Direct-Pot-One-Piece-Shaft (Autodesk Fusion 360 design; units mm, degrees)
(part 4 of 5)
work_plane "WorkPlane18" AlongDistance 3.9 ExtraOffset 0
sketch "Follower horizontal bore 45 degree roof" plane through (3.9, 0, 0) normal (1, 0, 0) x axis (0, 0, -1)
  line L1 (-14.9345, -32.0655) -> (-14.9345, -37.9345)
  line L2 (-17.869, -35) -> (-14.9345, -32.0655)
  line L3 (-14.9345, -37.9345) -> (-17.869, -35)
extrude "Extrude18" cut sketch "Follower horizontal bore 45 degree roof" along normal blind 16.2
work_plane "WorkPlane19" AlongDistance 3.9 ExtraOffset 0
sketch "Follower horizontal bore 45 degree roof (1)" plane through (3.9, 0, 0) normal (1, 0, 0) x axis (0, 0, -1)
  line L1 (-13.2021, 1.2021) -> (-13.2021, -1.2021)
  line L2 (-14.4042, 0) -> (-13.2021, 1.2021)
  line L3 (-13.2021, -1.2021) -> (-14.4042, 0)
extrude "Extrude19" cut sketch "Follower horizontal bore 45 degree roof (1)" along normal blind 16.2
work_plane "WorkPlane8" AlongDistance 49.65 ExtraOffset 0
sketch "Continuous support beneath lower output prong" plane through (49.65, 0, 0) normal (1, 0, 0) x axis (0, 0, -1)
  line L1 (-57, 2) -> (-57, -2)
  line L2 (-61, 2) -> (-57, 2)
  line L3 (-61, -2) -> (-61, 2)
  line L4 (-57, -2) -> (-61, -2)
extrude "Extrude8" add sketch "Continuous support beneath lower output prong" along normal blind 9
work_plane "WorkPlane11" AlongDistance 9 ExtraOffset 0
sketch "Upright grip head pocket roof" plane through (9, 0, 0) normal (1, 0, 0) x axis (0, 0, -1)
  line L1 (-182.192, -2.192) -> (-182.192, 2.192)
  line L2 (-184.3841, 0) -> (-182.192, -2.192)
  line L3 (-182.192, 2.192) -> (-184.3841, 0)
extrude "Extrude10" cut sketch "Upright grip head pocket roof" along normal blind 16
work_plane "WorkPlane12" AlongDistance 9 ExtraOffset 0
sketch "Upright grip head pocket roof (1)" plane through (9, 0, 0) normal (1, 0, 0) x axis (0, 0, -1)
  line L1 (-192.192, -2.192) -> (-192.192, 2.192)
  line L2 (-194.3841, 0) -> (-192.192, -2.192)
  line L3 (-192.192, 2.192) -> (-194.3841, 0)
extrude "Extrude11" cut sketch "Upright grip head pocket roof (1)" along normal blind 16
work_plane "WorkPlane19" AlongDistance -5 ExtraOffset 0
sketch "Direct cap-head rotor clamp seat" plane through (-5, 0, 0) normal (1, 0, 0) x axis (0, 0, -1)
  line L1 (-60, 22.5) -> (-60, 22)
  line L2 (-70, 22.5) -> (-60, 22.5)
  line L3 (-70, 22) -> (-70, 22.5)
  line L4 (-60, 22) -> (-70, 22)
extrude "Extrude19" add sketch "Direct cap-head rotor clamp seat" along normal blind 10
work_plane "WorkPlane20" AlongDistance 21.9 ExtraOffset 0
sketch "Restore rotor screw through raised seat" plane through (0, 21.9, 0) normal (0, 1, 0) x axis (1, 0, 0)
  circle C1 centre (0, -65) radius 1.7
extrude "Extrude20" cut sketch "Restore rotor screw through raised seat" along normal blind 0.7
work_plane "WorkPlane1" AlongDistance -39.35 ExtraOffset 0
sketch "Main shaft cap M3x8 cap head" plane through (-39.35, 0, 0) normal (1, 0, 0) x axis (0, 0, -1)
  circle C1 centre (-65, 0) radius 1.5
extrude "Extrude1" new body sketch "Main shaft cap M3x8 cap head" along normal blind 8 bodies "HARDWARE Main shaft cap M3x8 cap head"
work_plane "WorkPlane2" AlongDistance -42.35 ExtraOffset 0
sketch "Button head" plane through (-42.35, 0, 0) normal (1, 0, 0) x axis (0, 0, -1)
  circle C1 centre (-65, 0) radius 2.75
extrude "Extrude2" add sketch "Button head" along normal blind 3
work_plane "WorkPlane1" AlongDistance 2 ExtraOffset 0
sketch "Cam M3x10 cap head -45" plane through (2, 0, 0) normal (1, 0, 0) x axis (0, 0, -1)
  circle C1 centre (-39.5442, 25.4558) radius 1.5
extrude "Extrude1" new body sketch "Cam M3x10 cap head -45" along normal blind 10 bodies "HARDWARE Cam M3x10 cap head -45"
work_plane "WorkPlane2" AlongDistance 12 ExtraOffset 0
sketch "Button head" plane through (12, 0, 0) normal (1, 0, 0) x axis (0, 0, -1)
  circle C1 centre (-39.5442, 25.4558) radius 2.75
extrude "Extrude2" add sketch "Button head" along normal blind 3
work_plane "WorkPlane1" AlongDistance 2 ExtraOffset 0
sketch "Cam M3x10 cap head 0" plane through (2, 0, 0) normal (1, 0, 0) x axis (0, 0, -1)
  circle C1 centre (-29, 0) radius 1.5
extrude "Extrude1" new body sketch "Cam M3x10 cap head 0" along normal blind 10 bodies "HARDWARE Cam M3x10 cap head 0"
work_plane "WorkPlane2" AlongDistance 12 ExtraOffset 0
sketch "Button head" plane through (12, 0, 0) normal (1, 0, 0) x axis (0, 0, -1)
  circle C1 centre (-29, 0) radius 2.75
extrude "Extrude2" add sketch "Button head" along normal blind 3
work_plane "WorkPlane1" AlongDistance 2 ExtraOffset 0
sketch "Cam M3x10 cap head 45" plane through (2, 0, 0) normal (1, 0, 0) x axis (0, 0, -1)
  circle C1 centre (-39.5442, -25.4558) radius 1.5
extrude "Extrude1" new body sketch "Cam M3x10 cap head 45" along normal blind 10 bodies "HARDWARE Cam M3x10 cap head 45"
work_plane "WorkPlane2" AlongDistance 12 ExtraOffset 0
sketch "Button head" plane through (12, 0, 0) normal (1, 0, 0) x axis (0, 0, -1)
  circle C1 centre (-39.5442, -25.4558) radius 2.75
extrude "Extrude2" add sketch "Button head" along normal blind 3
work_plane "WorkPlane1" AlongDistance 0 ExtraOffset 0
sketch "Roller axle M3x20 cap head" plane through (0, 0, 0) normal (1, 0, 0) x axis (0, 0, -1)
  circle C1 centre (-12, 0) radius 1.5
extrude "Extrude1" new body sketch "Roller axle M3x20 cap head" along normal blind 20 bodies "HARDWARE Roller axle M3x20 cap head"
work_plane "WorkPlane2" AlongDistance 20 ExtraOffset 0
sketch "Button head" plane through (20, 0, 0) normal (1, 0, 0) x axis (0, 0, -1)
  circle C1 centre (-12, 0) radius 2.75
extrude "Extrude2" add sketch "Button head" along normal blind 3
work_plane "WorkPlane1" AlongDistance -36 ExtraOffset 0
sketch "Crossblock M3x20 cap head (-62, -1)" plane through (-36, 0, 0) normal (1, 0, 0) x axis (0, 0, -1)
  circle C1 centre (-53.5, -62) radius 1.5
extrude "Extrude1" new body sketch "Crossblock M3x20 cap head (-62, -1)" along normal blind 20 bodies "HARDWARE Crossblock M3x20 cap head (-62, -1)"
work_plane "WorkPlane2" AlongDistance -39 ExtraOffset 0
sketch "Button head" plane through (-39, 0, 0) normal (1, 0, 0) x axis (0, 0, -1)
  circle C1 centre (-53.5, -62) radius 2.75
extrude "Extrude2" add sketch "Button head" along normal blind 3
work_plane "WorkPlane1" AlongDistance 16 ExtraOffset 0
sketch "Crossblock M3x20 cap head (-62, 1)" plane through (16, 0, 0) normal (1, 0, 0) x axis (0, 0, -1)
  circle C1 centre (-53.5, -62) radius 1.5
extrude "Extrude1" new body sketch "Crossblock M3x20 cap head (-62, 1)" along normal blind 20 bodies "HARDWARE Crossblock M3x20 cap head (-62, 1)"
work_plane "WorkPlane2" AlongDistance 36 ExtraOffset 0
sketch "Button head" plane through (36, 0, 0) normal (1, 0, 0) x axis (0, 0, -1)
  circle C1 centre (-53.5, -62) radius 2.75
extrude "Extrude2" add sketch "Button head" along normal blind 3
work_plane "WorkPlane1" AlongDistance -36 ExtraOffset 0
sketch "Crossblock M3x20 cap head (-70, -1)" plane through (-36, 0, 0) normal (1, 0, 0) x axis (0, 0, -1)
  circle C1 centre (-53.5, -70) radius 1.5
extrude "Extrude1" new body sketch "Crossblock M3x20 cap head (-70, -1)" along normal blind 20 bodies "HARDWARE Crossblock M3x20 cap head (-70, -1)"
work_plane "WorkPlane2" AlongDistance -39 ExtraOffset 0
sketch "Button head" plane through (-39, 0, 0) normal (1, 0, 0) x axis (0, 0, -1)
  circle C1 centre (-53.5, -70) radius 2.75
extrude "Extrude2" add sketch "Button head" along normal blind 3
work_plane "WorkPlane1" AlongDistance 16 ExtraOffset 0
sketch "Crossblock M3x20 cap head (-70, 1)" plane through (16, 0, 0) normal (1, 0, 0) x axis (0, 0, -1)
  circle C1 centre (-53.5, -70) radius 1.5
extrude "Extrude1" new body sketch "Crossblock M3x20 cap head (-70, 1)" along normal blind 20 bodies "HARDWARE Crossblock M3x20 cap head (-70, 1)"
work_plane "WorkPlane2" AlongDistance 36 ExtraOffset 0
sketch "Button head" plane through (36, 0, 0) normal (1, 0, 0) x axis (0, 0, -1)
  circle C1 centre (-53.5, -70) radius 2.75
extrude "Extrude2" add sketch "Button head" along normal blind 3
work_plane "WorkPlane1" AlongDistance 6.5 ExtraOffset 0
sketch "Rotor clamp M3x16 cap head" plane through (0, 6.5, 0) normal (0, 1, 0) x axis (1, 0, 0)
  circle C1 centre (0, -65) radius 1.5
extrude "Extrude1" new body sketch "Rotor clamp M3x16 cap head" along normal blind 16 bodies "HARDWARE Rotor clamp M3x16 cap head"
work_plane "WorkPlane2" AlongDistance 22.5 ExtraOffset 0
sketch "Button head" plane through (0, 22.5, 0) normal (0, 1, 0) x axis (1, 0, 0)
  circle C1 centre (0, -65) radius 2.75
extrude "Extrude2" add sketch "Button head" along normal blind 3
work_plane "WorkPlane20" AlongDistance 3.9 ExtraOffset 0
sketch "Restore axle bore after adding print feet" plane through (3.9, 0, 0) normal (1, 0, 0) x axis (0, 0, -1)
  circle C1 centre (-12, 0) radius 1.7
extrude "Extrude20" cut sketch "Restore axle bore after adding print feet" along normal blind 16.2
work_plane "WorkPlane21" AlongDistance 3.9 ExtraOffset 0
sketch "Restore nut installation recess after print foot" plane through (3.9, 0, 0) normal (1, 0, 0) x axis (0, 0, -1)
  line L1 (-14.9, 1.6743) -> (-12, 3.3486)
  line L2 (-14.9, -1.6743) -> (-14.9, 1.6743)
  line L3 (-12, -3.3486) -> (-14.9, -1.6743)
  line L4 (-9.1, -1.6743) -> (-12, -3.3486)
  line L5 (-9.1, 1.6743) -> (-9.1, -1.6743)
  line L6 (-12, 3.3486) -> (-9.1, 1.6743)
extrude "Extrude21" cut sketch "Restore nut installation recess after print foot" along normal blind 1.6
work_plane "WorkPlane3" AlongDistance 8 ExtraOffset 0
sketch "Retain one mm preload travel before head meets collar" plane through (8, 0, 0) normal (1, 0, 0) x axis (0, 0, -1)
  line L1 (-56, -51) -> (-56, -59)
  line L2 (-57.1, -51) -> (-56, -51)
  line L3 (-57.1, -59) -> (-57.1, -51)
  line L4 (-56, -59) -> (-57.1, -59)
extrude "Extrude3" cut sketch "Retain one mm preload travel before head meets collar" along normal blind 8
work_plane "WorkPlane63" AlongDistance 20.8 ExtraOffset 0
sketch "Clear stocked carriage screw tip beyond insert" plane through (0, 20.8, 0) normal (0, 1, 0) x axis (1, 0, 0)
  circle C1 centre (60.15, -65) radius 1.7
extrude "Extrude63" cut sketch "Clear stocked carriage screw tip beyond insert" along normal blind 0.6
work_plane "WorkPlane64" AlongDistance -21.4 ExtraOffset 0
sketch "Clear stocked carriage screw tip beyond insert (1)" plane through (0, -21.4, 0) normal (0, 1, 0) x axis (1, 0, 0)
  circle C1 centre (60.15, -65) radius 1.7
extrude "Extrude64" cut sketch "Clear stocked carriage screw tip beyond insert (1)" along normal blind 0.6
work_plane "WorkPlane22" AlongDistance -2.5 ExtraOffset 0
sketch "Support-free lower ramp under left inner-race pad" plane through (0, -2.5, 0) normal (0, 1, 0) x axis (1, 0, 0)
  line L1 (8.1, -9.5) -> (7, -9.5)
  line L2 (8.1, -10.7) -> (8.1, -9.5)
  line L3 (7, -9.6) -> (8.1, -10.7)
  line L4 (7, -9.5) -> (7, -9.6)
extrude "Extrude22" cut sketch "Support-free lower ramp under left inner-race pad" along normal blind 5
work_plane "WorkPlane23" AlongDistance -2.5 ExtraOffset 0
sketch "Support-free lower ramp under right inner-race pad" plane through (0, -2.5, 0) normal (0, 1, 0) x axis (1, 0, 0)
  line L1 (17, -9.5) -> (15.9, -9.5)
  line L2 (17, -9.6) -> (17, -9.5)
  line L3 (15.9, -10.7) -> (17, -9.6)
  line L4 (15.9, -9.5) -> (15.9, -10.7)
extrude "Extrude23" cut sketch "Support-free lower ramp under right inner-race pad" along normal blind 5
ground "Pin94"
ground "Pin95"
ground "Pin96"
ground "Pin97"
ground "Pin98"
ground "Pin99"
ground "Pin100"
ground "Pin101"
ground "Pin102"
ground "Pin103"
ground "Pin104"
ground "Pin105"
ground "Pin106"
ground "Pin107"
ground "Pin108"
ground "Pin109"
ground "Pin110"
ground "Pin111"
ground "Pin112"
ground "Pin113"
ground "Pin114"
ground "Pin115"
ground "Pin116"
ground "Pin120"
ground "Pin121"
ground "Pin122"
ground "Pin123"
ground "Unpin124"
ground "Unpin125"
ground "Unpin126"
ground "Unpin127"
ground "Unpin128"
ground "Unpin129"
ground "Unpin130"
ground "Unpin131"
ground "Unpin132"
ground "Unpin133"
ground "Unpin134"
ground "Unpin135"
ground "Unpin136"
ground "Unpin137"
ground "Unpin138"
ground "Unpin139"
ground "Unpin140"
ground "Unpin141"
ground "Unpin142"
ground "Unpin143"
ground "Unpin144"
ground "Unpin145"
ground "Unpin146"
ground "Unpin147"
ground "Unpin148"
ground "Unpin149"
ground "Unpin150"
ground "Unpin151"
ground "Unpin152"
ground "Unpin153"
ground "Unpin154"
ground "Unpin155"
ground "Unpin156"
ground "Unpin160"
ground "Unpin161"
ground "Unpin162"
ground "Unpin163"
split "Split1" bodies "P04 Right bush upper half"
work_plane "WorkPlane68" AlongDistance -36.1 ExtraOffset 0
sketch "Remove former rail tab before recess" plane through (-36.1, 0, 0) normal (1, 0, 0) x axis (0, 0, -1)
  line L1 (-54.9, -74.5) -> (-54.9, -96)
  line L2 (-64.2, -74.5) -> (-54.9, -74.5)
  line L3 (-64.2, -96) -> (-64.2, -74.5)
  line L4 (-54.9, -96) -> (-64.2, -96)
extrude "Extrude68" cut sketch "Remove former rail tab before recess" along normal blind 12.2
work_plane "WorkPlane69" AlongDistance -36 ExtraOffset 0
sketch "Continuous recessed hanging tower" plane through (-36, 0, 0) normal (1, 0, 0) x axis (0, 0, -1)
  line L1 (-55, -63) -> (-55, -74.5)
  line L2 (-99, -63) -> (-55, -63)
  line L3 (-99, -74.5) -> (-99, -63)
  line L4 (-55, -74.5) -> (-99, -74.5)
extrude "Extrude69" add sketch "Continuous recessed hanging tower" along normal blind 12
work_plane "WorkPlane70" AlongDistance -36 ExtraOffset 0
sketch "Top rail seat unchanged after 35 mm drop" plane through (-36, 0, 0) normal (1, 0, 0) x axis (0, 0, -1)
  line L1 (-90, -63) -> (-90, -95)
  line L2 (-99, -63) -> (-90, -63)
  line L3 (-99, -95) -> (-99, -63)
  line L4 (-90, -95) -> (-99, -95)
extrude "Extrude70" add sketch "Top rail seat unchanged after 35 mm drop" along normal blind 12
work_plane "WorkPlane71" AlongDistance 89.9 ExtraOffset 0
sketch "Rail clearance at retained world seat" plane through (0, 0, 89.9) normal (0, 0, 1) x axis (1, 0, 0)
  circle C1 centre (-30, -85) radius 2.7
extrude "Extrude71" cut sketch "Rail clearance at retained world seat" along normal blind 9.2
work_plane "WorkPlane72" AlongDistance 89.9 ExtraOffset 0
sketch "Rail bore 45 degree print roof" plane through (0, 0, 89.9) normal (0, 0, 1) x axis (1, 0, 0)
  line L1 (-28.0908, -83.0908) -> (-28.0908, -86.9092)
  line L2 (-26.1816, -85) -> (-28.0908, -83.0908)
  line L3 (-28.0908, -86.9092) -> (-26.1816, -85)
extrude "Extrude72" cut sketch "Rail bore 45 degree print roof" along normal blind 9.2
work_plane "WorkPlane73" AlongDistance -36.1 ExtraOffset 0
sketch "Remove former rail tab before recess (1)" plane through (-36.1, 0, 0) normal (1, 0, 0) x axis (0, 0, -1)
  line L1 (-54.9, 96) -> (-54.9, 74.5)
  line L2 (-64.2, 96) -> (-54.9, 96)
  line L3 (-64.2, 74.5) -> (-64.2, 96)
  line L4 (-54.9, 74.5) -> (-64.2, 74.5)
extrude "Extrude73" cut sketch "Remove former rail tab before recess (1)" along normal blind 12.2
work_plane "WorkPlane74" AlongDistance -36 ExtraOffset 0
sketch "Continuous recessed hanging tower (1)" plane through (-36, 0, 0) normal (1, 0, 0) x axis (0, 0, -1)
  line L1 (-55, 74.5) -> (-55, 63)
  line L2 (-99, 74.5) -> (-55, 74.5)
  line L3 (-99, 63) -> (-99, 74.5)
  line L4 (-55, 63) -> (-99, 63)
extrude "Extrude74" add sketch "Continuous recessed hanging tower (1)" along normal blind 12
work_plane "WorkPlane75" AlongDistance -36 ExtraOffset 0
sketch "Top rail seat unchanged after 35 mm drop (1)" plane through (-36, 0, 0) normal (1, 0, 0) x axis (0, 0, -1)
  line L1 (-90, 95) -> (-90, 63)
  line L2 (-99, 95) -> (-90, 95)
  line L3 (-99, 63) -> (-99, 95)
  line L4 (-90, 63) -> (-99, 63)
extrude "Extrude75" add sketch "Top rail seat unchanged after 35 mm drop (1)" along normal blind 12
work_plane "WorkPlane76" AlongDistance 89.9 ExtraOffset 0
sketch "Rail clearance at retained world seat (1)" plane through (0, 0, 89.9) normal (0, 0, 1) x axis (1, 0, 0)
  circle C1 centre (-30, 85) radius 2.7
extrude "Extrude76" cut sketch "Rail clearance at retained world seat (1)" along normal blind 9.2
work_plane "WorkPlane77" AlongDistance 89.9 ExtraOffset 0
sketch "Rail bore 45 degree print roof (1)" plane through (0, 0, 89.9) normal (0, 0, 1) x axis (1, 0, 0)
  line L1 (-28.0908, 86.9092) -> (-28.0908, 83.0908)
  line L2 (-26.1816, 85) -> (-28.0908, 86.9092)
  line L3 (-28.0908, 83.0908) -> (-26.1816, 85)
extrude "Extrude77" cut sketch "Rail bore 45 degree print roof (1)" along normal blind 9.2
work_plane "WorkPlane65" AlongDistance 23.9 ExtraOffset 0
sketch "Remove former rail tab before recess" plane through (23.9, 0, 0) normal (1, 0, 0) x axis (0, 0, -1)
  line L1 (-54.9, -74.5) -> (-54.9, -96)
  line L2 (-64.2, -74.5) -> (-54.9, -74.5)
  line L3 (-64.2, -96) -> (-64.2, -74.5)
  line L4 (-54.9, -96) -> (-64.2, -96)
extrude "Extrude65" cut sketch "Remove former rail tab before recess" along normal blind 12.2
work_plane "WorkPlane66" AlongDistance 24 ExtraOffset 0
sketch "Continuous recessed hanging tower" plane through (24, 0, 0) normal (1, 0, 0) x axis (0, 0, -1)
  line L1 (-55, -63) -> (-55, -74.5)
  line L2 (-99, -63) -> (-55, -63)
  line L3 (-99, -74.5) -> (-99, -63)
  line L4 (-55, -74.5) -> (-99, -74.5)
extrude "Extrude66" add sketch "Continuous recessed hanging tower" along normal blind 12
work_plane "WorkPlane67" AlongDistance 24 ExtraOffset 0
sketch "Top rail seat unchanged after 35 mm drop" plane through (24, 0, 0) normal (1, 0, 0) x axis (0, 0, -1)
  line L1 (-90, -63) -> (-90, -95)
  line L2 (-99, -63) -> (-90, -63)
  line L3 (-99, -95) -> (-99, -63)
  line L4 (-90, -95) -> (-99, -95)
extrude "Extrude67" add sketch "Top rail seat unchanged after 35 mm drop" along normal blind 12
work_plane "WorkPlane68" AlongDistance 89.9 ExtraOffset 0
sketch "Rail clearance at retained world seat" plane through (0, 0, 89.9) normal (0, 0, 1) x axis (1, 0, 0)
  circle C1 centre (30, -85) radius 2.7
extrude "Extrude68" cut sketch "Rail clearance at retained world seat" along normal blind 9.2
work_plane "WorkPlane69" AlongDistance 89.9 ExtraOffset 0
sketch "Rail bore 45 degree print roof" plane through (0, 0, 89.9) normal (0, 0, 1) x axis (1, 0, 0)
  line L1 (31.9092, -83.0908) -> (31.9092, -86.9092)
  line L2 (33.8184, -85) -> (31.9092, -83.0908)
  line L3 (31.9092, -86.9092) -> (33.8184, -85)
extrude "Extrude69" cut sketch "Rail bore 45 degree print roof" along normal blind 9.2
work_plane "WorkPlane70" AlongDistance 23.9 ExtraOffset 0
sketch "Remove former rail tab before recess (1)" plane through (23.9, 0, 0) normal (1, 0, 0) x axis (0, 0, -1)
  line L1 (-54.9, 96) -> (-54.9, 74.5)
  line L2 (-64.2, 96) -> (-54.9, 96)
  line L3 (-64.2, 74.5) -> (-64.2, 96)
  line L4 (-54.9, 74.5) -> (-64.2, 74.5)
extrude "Extrude70" cut sketch "Remove former rail tab before recess (1)" along normal blind 12.2
work_plane "WorkPlane71" AlongDistance 24 ExtraOffset 0
sketch "Continuous recessed hanging tower (1)" plane through (24, 0, 0) normal (1, 0, 0) x axis (0, 0, -1)
  line L1 (-55, 74.5) -> (-55, 63)
  line L2 (-99, 74.5) -> (-55, 74.5)
  line L3 (-99, 63) -> (-99, 74.5)
  line L4 (-55, 63) -> (-99, 63)
extrude "Extrude71" add sketch "Continuous recessed hanging tower (1)" along normal blind 12
work_plane "WorkPlane72" AlongDistance 24 ExtraOffset 0
sketch "Top rail seat unchanged after 35 mm drop (1)" plane through (24, 0, 0) normal (1, 0, 0) x axis (0, 0, -1)
  line L1 (-90, 95) -> (-90, 63)
  line L2 (-99, 95) -> (-90, 95)
  line L3 (-99, 63) -> (-99, 95)
  line L4 (-90, 63) -> (-99, 63)
extrude "Extrude72" add sketch "Top rail seat unchanged after 35 mm drop (1)" along normal blind 12
work_plane "WorkPlane73" AlongDistance 89.9 ExtraOffset 0
sketch "Rail clearance at retained world seat (1)" plane through (0, 0, 89.9) normal (0, 0, 1) x axis (1, 0, 0)
  circle C1 centre (30, 85) radius 2.7
extrude "Extrude73" cut sketch "Rail clearance at retained world seat (1)" along normal blind 9.2
work_plane "WorkPlane74" AlongDistance 89.9 ExtraOffset 0
sketch "Rail bore 45 degree print roof (1)" plane through (0, 0, 89.9) normal (0, 0, 1) x axis (1, 0, 0)
  line L1 (31.9092, 86.9092) -> (31.9092, 83.0908)
  line L2 (33.8184, 85) -> (31.9092, 86.9092)
  line L3 (31.9092, 83.0908) -> (33.8184, 85)
extrude "Extrude74" cut sketch "Rail bore 45 degree print roof (1)" along normal blind 9.2
work_plane "WorkPlane78" AlongDistance -31.5 ExtraOffset 0
sketch "Counterbore first anchored bridge relief" plane through (-31.5, 0, 0) normal (1, 0, 0) x axis (0, 0, -1)
  line L1 (-77.9754, -30.8652) -> (-77.9754, -37.0652)
  line L2 (-81.3754, -30.8652) -> (-77.9754, -30.8652)
  line L3 (-81.3754, -37.0652) -> (-81.3754, -30.8652)
  line L4 (-77.9754, -37.0652) -> (-81.3754, -37.0652)
extrude "Extrude78" cut sketch "Counterbore first anchored bridge relief" along normal blind 0.2
work_plane "WorkPlane79" AlongDistance -31.3 ExtraOffset 0
sketch "Counterbore crossed bridge relief" plane through (-31.3, 0, 0) normal (1, 0, 0) x axis (0, 0, -1)
  line L1 (-77.9754, -32.2652) -> (-77.9754, -35.6652)
  line L2 (-81.3754, -32.2652) -> (-77.9754, -32.2652)
  line L3 (-81.3754, -35.6652) -> (-81.3754, -32.2652)
  line L4 (-77.9754, -35.6652) -> (-81.3754, -35.6652)
extrude "Extrude79" cut sketch "Counterbore crossed bridge relief" along normal blind 0.2
work_plane "WorkPlane80" AlongDistance -31.5 ExtraOffset 0
sketch "Counterbore first anchored bridge relief (1)" plane through (-31.5, 0, 0) normal (1, 0, 0) x axis (0, 0, -1)
  line L1 (-77.9754, 37.0652) -> (-77.9754, 30.8652)
  line L2 (-81.3754, 37.0652) -> (-77.9754, 37.0652)
  line L3 (-81.3754, 30.8652) -> (-81.3754, 37.0652)
  line L4 (-77.9754, 30.8652) -> (-81.3754, 30.8652)
extrude "Extrude80" cut sketch "Counterbore first anchored bridge relief (1)" along normal blind 0.2
work_plane "WorkPlane81" AlongDistance -31.3 ExtraOffset 0
sketch "Counterbore crossed bridge relief (1)" plane through (-31.3, 0, 0) normal (1, 0, 0) x axis (0, 0, -1)
  line L1 (-77.9754, 35.6652) -> (-77.9754, 32.2652)
  line L2 (-81.3754, 35.6652) -> (-77.9754, 35.6652)
  line L3 (-81.3754, 32.2652) -> (-81.3754, 35.6652)
  line L4 (-77.9754, 32.2652) -> (-81.3754, 32.2652)
extrude "Extrude81" cut sketch "Counterbore crossed bridge relief (1)" along normal blind 0.2
work_plane "WorkPlane75" AlongDistance -28.1 ExtraOffset 0
sketch "Close old insert pocket" plane through (0, -28.1, 0) normal (0, 1, 0) x axis (1, 0, 0)
  circle C1 centre (60.15, -65) radius 2.01
extrude "Extrude75" add sketch "Close old insert pocket" along normal blind 6.8
work_plane "WorkPlane76" AlongDistance 62.95 ExtraOffset 0
sketch "Measured pot panel inward clearance" plane through (62.95, 0, 0) normal (1, 0, 0) x axis (0, 0, -1)
  line L1 (-55.9, -18) -> (-55.9, -28)
  line L2 (-81.1, -18) -> (-55.9, -18)
  line L3 (-81.1, -28) -> (-81.1, -18)
  line L4 (-55.9, -28) -> (-81.1, -28)
extrude "Extrude76" cut sketch "Measured pot panel inward clearance" along normal blind 3.35
work_plane "WorkPlane77" AlongDistance -25 ExtraOffset 0
sketch "Side-loaded carriage nut" plane through (0, -25, 0) normal (0, 1, 0) x axis (1, 0, 0)
  line L1 (59.8243, -67.9) -> (61.4986, -65)
  line L2 (56.4757, -67.9) -> (59.8243, -67.9)
  line L3 (54.8014, -65) -> (56.4757, -67.9)
  line L4 (56.4757, -62.1) -> (54.8014, -65)
  line L5 (59.8243, -62.1) -> (56.4757, -62.1)
  line L6 (61.4986, -65) -> (59.8243, -62.1)
extrude "Extrude77" cut sketch "Side-loaded carriage nut" along normal blind 2.6
work_plane "WorkPlane78" AlongDistance 58.15 ExtraOffset 0
sketch "Nut insertion from panel end" plane through (58.15, 0, 0) normal (1, 0, 0) x axis (0, 0, -1)
  line L1 (-62.1, -22.4) -> (-62.1, -25)
  line L2 (-67.9, -22.4) -> (-62.1, -22.4)
  line L3 (-67.9, -25) -> (-67.9, -22.4)
  line L4 (-62.1, -25) -> (-67.9, -25)
extrude "Extrude78" cut sketch "Nut insertion from panel end" along normal blind 4.9
work_plane "WorkPlane79" AlongDistance -28.1 ExtraOffset 0
sketch "Carriage screw to captive nut" plane through (0, -28.1, 0) normal (0, 1, 0) x axis (1, 0, 0)
  circle C1 centre (58.15, -65) radius 1.7
extrude "Extrude79" cut sketch "Carriage screw to captive nut" along normal blind 7.3
work_plane "WorkPlane80" AlongDistance 21.3 ExtraOffset 0
sketch "Close old insert pocket (1)" plane through (0, 21.3, 0) normal (0, 1, 0) x axis (1, 0, 0)
  circle C1 centre (60.15, -65) radius 2.01
extrude "Extrude80" add sketch "Close old insert pocket (1)" along normal blind 6.8
work_plane "WorkPlane81" AlongDistance 62.95 ExtraOffset 0
sketch "Measured pot panel inward clearance (1)" plane through (62.95, 0, 0) normal (1, 0, 0) x axis (0, 0, -1)
  line L1 (-55.9, 28) -> (-55.9, 18)
  line L2 (-81.1, 28) -> (-55.9, 28)
  line L3 (-81.1, 18) -> (-81.1, 28)
  line L4 (-55.9, 18) -> (-81.1, 18)
extrude "Extrude81" cut sketch "Measured pot panel inward clearance (1)" along normal blind 3.35
work_plane "WorkPlane82" AlongDistance 22.4 ExtraOffset 0
sketch "Side-loaded carriage nut (1)" plane through (0, 22.4, 0) normal (0, 1, 0) x axis (1, 0, 0)
  line L1 (59.8243, -67.9) -> (61.4986, -65)
  line L2 (56.4757, -67.9) -> (59.8243, -67.9)
  line L3 (54.8014, -65) -> (56.4757, -67.9)
  line L4 (56.4757, -62.1) -> (54.8014, -65)
  line L5 (59.8243, -62.1) -> (56.4757, -62.1)
  line L6 (61.4986, -65) -> (59.8243, -62.1)
extrude "Extrude82" cut sketch "Side-loaded carriage nut (1)" along normal blind 2.6
work_plane "WorkPlane83" AlongDistance 58.15 ExtraOffset 0
sketch "Nut insertion from panel end (1)" plane through (58.15, 0, 0) normal (1, 0, 0) x axis (0, 0, -1)
  line L1 (-62.1, 25) -> (-62.1, 22.4)
  line L2 (-67.9, 25) -> (-62.1, 25)
  line L3 (-67.9, 22.4) -> (-67.9, 25)
  line L4 (-62.1, 22.4) -> (-67.9, 22.4)
extrude "Extrude83" cut sketch "Nut insertion from panel end (1)" along normal blind 4.9
work_plane "WorkPlane84" AlongDistance 20.8 ExtraOffset 0
sketch "Carriage screw to captive nut (1)" plane through (0, 20.8, 0) normal (0, 1, 0) x axis (1, 0, 0)
  circle C1 centre (58.15, -65) radius 1.7
extrude "Extrude84" cut sketch "Carriage screw to captive nut (1)" along normal blind 7.3
work_plane "WorkPlane1" AlongDistance 65.95 ExtraOffset 0
sketch "Measured body 11.2 x 9.5 x 6.6" plane through (65.95, 0, 0) normal (1, 0, 0) x axis (0, 0, -1)
  line L1 (-60.25, 5.6) -> (-60.25, -5.6)
  line L2 (-69.75, 5.6) -> (-60.25, 5.6)
  line L3 (-69.75, -5.6) -> (-69.75, 5.6)
  line L4 (-60.25, -5.6) -> (-69.75, -5.6)
extrude "Extrude1" new body sketch "Measured body 11.2 x 9.5 x 6.6" along normal blind 6.6
work_plane "WorkPlane2" AlongDistance 58.95 ExtraOffset 0
sketch "Inferred 7 mm M7 bushing" plane through (58.95, 0, 0) normal (1, 0, 0) x axis (0, 0, -1)
  circle C1 centre (-65, 0) radius 3.5
extrude "Extrude2" add sketch "Inferred 7 mm M7 bushing" along normal blind 7
work_plane "WorkPlane3" AlongDistance 50.95 ExtraOffset 0
sketch "Measured 8 mm rotating shaft" plane through (50.95, 0, 0) normal (1, 0, 0) x axis (0, 0, -1)
  circle C1 centre (-65, 0) radius 3
extrude "Extrude3" add sketch "Measured 8 mm rotating shaft" along normal blind 8
work_plane "WorkPlane1" AlongDistance 62.45 ExtraOffset 0
sketch "Pot supplied washer assumed" plane through (62.45, 0, 0) normal (1, 0, 0) x axis (0, 0, -1)
  circle C1 centre (-65, 0) radius 6
extrude "Extrude1" new body sketch "Pot supplied washer assumed" along normal blind 0.5 bodies "HARDWARE Pot supplied washer assumed"
work_plane "WorkPlane2" AlongDistance 62.35 ExtraOffset 0
sketch "Washer clearance" plane through (62.35, 0, 0) normal (1, 0, 0) x axis (0, 0, -1)
  circle C1 centre (-65, 0) radius 3.6
extrude "Extrude2" cut sketch "Washer clearance" along normal blind 0.7
work_plane "WorkPlane1" AlongDistance 60.45 ExtraOffset 0
sketch "Pot supplied M7 nut assumed" plane through (60.45, 0, 0) normal (1, 0, 0) x axis (0, 0, -1)
  line L1 (-70.5, 3.1754) -> (-65, 6.3509)
  line L2 (-70.5, -3.1754) -> (-70.5, 3.1754)
  line L3 (-65, -6.3509) -> (-70.5, -3.1754)
  line L4 (-59.5, -3.1754) -> (-65, -6.3509)
  line L5 (-59.5, 3.1754) -> (-59.5, -3.1754)
  line L6 (-65, 6.3509) -> (-59.5, 3.1754)
extrude "Extrude1" new body sketch "Pot supplied M7 nut assumed" along normal blind 2 bodies "HARDWARE Pot supplied M7 nut assumed"
work_plane "WorkPlane2" AlongDistance 60.35 ExtraOffset 0
sketch "Thread envelope" plane through (60.35, 0, 0) normal (1, 0, 0) x axis (0, 0, -1)
  circle C1 centre (-65, 0) radius 3.5
extrude "Extrude2" cut sketch "Thread envelope" along normal blind 2.2
work_plane "WorkPlane1" AlongDistance -24.9 ExtraOffset 0
sketch "Carriage captured M3 -1" plane through (0, -24.9, 0) normal (0, 1, 0) x axis (1, 0, 0)
  line L1 (59.7377, -67.75) -> (61.3254, -65)
  line L2 (56.5623, -67.75) -> (59.7377, -67.75)
  line L3 (54.9746, -65) -> (56.5623, -67.75)
  line L4 (56.5623, -62.25) -> (54.9746, -65)
  line L5 (59.7377, -62.25) -> (56.5623, -62.25)
  line L6 (61.3254, -65) -> (59.7377, -62.25)
extrude "Extrude1" new body sketch "Carriage captured M3 -1" along normal blind 2.4 bodies "HARDWARE Carriage captured M3 -1"
work_plane "WorkPlane2" AlongDistance -25 ExtraOffset 0
sketch "Thread envelope" plane through (0, -25, 0) normal (0, 1, 0) x axis (1, 0, 0)
  circle C1 centre (58.15, -65) radius 1.5
extrude "Extrude2" cut sketch "Thread envelope" along normal blind 2.6
work_plane "WorkPlane1" AlongDistance 22.5 ExtraOffset 0
sketch "Carriage captured M3 1" plane through (0, 22.5, 0) normal (0, 1, 0) x axis (1, 0, 0)
  line L1 (59.7377, -67.75) -> (61.3254, -65)
  line L2 (56.5623, -67.75) -> (59.7377, -67.75)
  line L3 (54.9746, -65) -> (56.5623, -67.75)
  line L4 (56.5623, -62.25) -> (54.9746, -65)
  line L5 (59.7377, -62.25) -> (56.5623, -62.25)
  line L6 (61.3254, -65) -> (59.7377, -62.25)
extrude "Extrude1" new body sketch "Carriage captured M3 1" along normal blind 2.4 bodies "HARDWARE Carriage captured M3 1"
work_plane "WorkPlane2" AlongDistance 22.4 ExtraOffset 0
sketch "Thread envelope" plane through (0, 22.4, 0) normal (0, 1, 0) x axis (1, 0, 0)
  circle C1 centre (58.15, -65) radius 1.5
extrude "Extrude2" cut sketch "Thread envelope" along normal blind 2.6
work_plane "WorkPlane54" AlongDistance 38 ExtraOffset 0
sketch "Close insert pilot for captive nut conversion" plane through (0, 0, 38) normal (0, 0, 1) x axis (1, 0, 0)
  circle C1 centre (4, -55) radius 2.01
extrude "Extrude54" add sketch "Close insert pilot for captive nut conversion" along normal blind 6.8
work_plane "WorkPlane55" AlongDistance 37.9 ExtraOffset 0
sketch "M3 clearance through nut interface" plane through (0, 0, 37.9) normal (0, 0, 1) x axis (1, 0, 0)
  circle C1 centre (4, -55) radius 1.7
extrude "Extrude55" cut sketch "M3 clearance through nut interface" along normal blind 7
work_plane "WorkPlane56" AlongDistance 38 ExtraOffset 0
sketch "Close insert pilot for captive nut conversion (1)" plane through (0, 0, 38) normal (0, 0, 1) x axis (1, 0, 0)
  circle C1 centre (12, -55) radius 2.01
extrude "Extrude56" add sketch "Close insert pilot for captive nut conversion (1)" along normal blind 6.8
work_plane "WorkPlane57" AlongDistance 37.9 ExtraOffset 0
sketch "M3 clearance through nut interface (1)" plane through (0, 0, 37.9) normal (0, 0, 1) x axis (1, 0, 0)
  circle C1 centre (12, -55) radius 1.7
extrude "Extrude57" cut sketch "M3 clearance through nut interface (1)" along normal blind 21.2
work_plane "WorkPlane58" AlongDistance 38 ExtraOffset 0
sketch "Close insert pilot for captive nut conversion (2)" plane through (0, 0, 38) normal (0, 0, 1) x axis (1, 0, 0)
  circle C1 centre (20, -55) radius 2.01
extrude "Extrude58" add sketch "Close insert pilot for captive nut conversion (2)" along normal blind 6.8
work_plane "WorkPlane59" AlongDistance 37.9 ExtraOffset 0
sketch "M3 clearance through nut interface (2)" plane through (0, 0, 37.9) normal (0, 0, 1) x axis (1, 0, 0)
  circle C1 centre (20, -55) radius 1.7
extrude "Extrude59" cut sketch "M3 clearance through nut interface (2)" along normal blind 7
work_plane "WorkPlane60" AlongDistance 37.9 ExtraOffset 0
sketch "Bottom loaded preload reaction nut" plane through (0, 0, 37.9) normal (0, 0, 1) x axis (1, 0, 0)
  line L1 (13.6743, -52.1) -> (15.3486, -55)
  line L2 (10.3257, -52.1) -> (13.6743, -52.1)
  line L3 (8.6514, -55) -> (10.3257, -52.1)
  line L4 (10.3257, -57.9) -> (8.6514, -55)
  line L5 (13.6743, -57.9) -> (10.3257, -57.9)
  line L6 (15.3486, -55) -> (13.6743, -57.9)
extrude "Extrude60" cut sketch "Bottom loaded preload reaction nut" along normal blind 2.7
work_plane "WorkPlane1" AlongDistance 38.1 ExtraOffset 0
sketch "Preload bottom reaction M3 nut" plane through (0, 0, 38.1) normal (0, 0, 1) x axis (1, 0, 0)
  line L1 (13.5877, -52.25) -> (15.1754, -55)
  line L2 (10.4123, -52.25) -> (13.5877, -52.25)
  line L3 (8.8246, -55) -> (10.4123, -52.25)
  line L4 (10.4123, -57.75) -> (8.8246, -55)
  line L5 (13.5877, -57.75) -> (10.4123, -57.75)
  line L6 (15.1754, -55) -> (13.5877, -57.75)
extrude "Extrude1" new body sketch "Preload bottom reaction M3 nut" along normal blind 2.4 bodies "HARDWARE Preload bottom reaction M3 nut"
work_plane "WorkPlane2" AlongDistance 38 ExtraOffset 0
sketch "Thread envelope" plane through (0, 0, 38) normal (0, 0, 1) x axis (1, 0, 0)
  circle C1 centre (12, -55) radius 1.5
extrude "Extrude2" cut sketch "Thread envelope" along normal blind 2.6
work_plane "WorkPlane61" AlongDistance 40.8 ExtraOffset 0
sketch "Guide captive nut with lower reaction shoulder" plane through (0, 0, 40.8) normal (0, 0, 1) x axis (1, 0, 0)
  line L1 (4, -51.6514) -> (6.9, -53.3257)
  line L2 (1.1, -53.3257) -> (4, -51.6514)
  line L3 (1.1, -56.6743) -> (1.1, -53.3257)
  line L4 (4, -58.3486) -> (1.1, -56.6743)
  line L5 (6.9, -56.6743) -> (4, -58.3486)
  line L6 (6.9, -53.3257) -> (6.9, -56.6743)
extrude "Extrude61" cut sketch "Guide captive nut with lower reaction shoulder" along normal blind 2.6
work_plane "WorkPlane62" AlongDistance 1.1 ExtraOffset 0
sketch "Guide nut rear installation slot" plane through (1.1, 0, 0) normal (1, 0, 0) x axis (0, 0, -1)
  line L1 (-40.8, -55) -> (-40.8, -74.1)
  line L2 (-43.4, -55) -> (-40.8, -55)
  line L3 (-43.4, -74.1) -> (-43.4, -55)
  line L4 (-40.8, -74.1) -> (-43.4, -74.1)
extrude "Extrude62" cut sketch "Guide nut rear installation slot" along normal blind 5.8
work_plane "WorkPlane63" AlongDistance 1.1 ExtraOffset 0
sketch "Guide nut first bridge relief" plane through (1.1, 0, 0) normal (1, 0, 0) x axis (0, 0, -1)
  line L1 (-40.6, -53.3) -> (-40.6, -56.7)
  line L2 (-40.8, -53.3) -> (-40.6, -53.3)
  line L3 (-40.8, -56.7) -> (-40.8, -53.3)
  line L4 (-40.6, -56.7) -> (-40.8, -56.7)
extrude "Extrude63" cut sketch "Guide nut first bridge relief" along normal blind 5.8
work_plane "WorkPlane64" AlongDistance 2.3 ExtraOffset 0
sketch "Guide nut crossed bridge relief" plane through (2.3, 0, 0) normal (1, 0, 0) x axis (0, 0, -1)
  line L1 (-40.4, -53.3) -> (-40.4, -56.7)
  line L2 (-40.6, -53.3) -> (-40.4, -53.3)
  line L3 (-40.6, -56.7) -> (-40.6, -53.3)
  line L4 (-40.4, -56.7) -> (-40.6, -56.7)
extrude "Extrude64" cut sketch "Guide nut crossed bridge relief" along normal blind 3.4
work_plane "WorkPlane1" AlongDistance 40.9 ExtraOffset 0
sketch "Guide nut envelope" plane through (0, 0, 40.9) normal (0, 0, 1) x axis (1, 0, 0)
  line L1 (4, -51.8246) -> (6.75, -53.4123)
  line L2 (1.25, -53.4123) -> (4, -51.8246)
  line L3 (1.25, -56.5877) -> (1.25, -53.4123)
  line L4 (4, -58.1754) -> (1.25, -56.5877)
  line L5 (6.75, -56.5877) -> (4, -58.1754)
  line L6 (6.75, -53.4123) -> (6.75, -56.5877)
extrude "Extrude1" new body sketch "Guide nut envelope" along normal blind 2.4
work_plane "WorkPlane2" AlongDistance 40.8 ExtraOffset 0
sketch "Guide nut thread" plane through (0, 0, 40.8) normal (0, 0, 1) x axis (1, 0, 0)
  circle C1 centre (4, -55) radius 1.5
extrude "Extrude2" cut sketch "Guide nut thread" along normal blind 2.6
work_plane "WorkPlane65" AlongDistance 40.8 ExtraOffset 0
sketch "Guide captive nut with lower reaction shoulder (1)" plane through (0, 0, 40.8) normal (0, 0, 1) x axis (1, 0, 0)
  line L1 (20, -51.6514) -> (22.9, -53.3257)
  line L2 (17.1, -53.3257) -> (20, -51.6514)
  line L3 (17.1, -56.6743) -> (17.1, -53.3257)
  line L4 (20, -58.3486) -> (17.1, -56.6743)
  line L5 (22.9, -56.6743) -> (20, -58.3486)
  line L6 (22.9, -53.3257) -> (22.9, -56.6743)
extrude "Extrude65" cut sketch "Guide captive nut with lower reaction shoulder (1)" along normal blind 2.6
work_plane "WorkPlane66" AlongDistance 17.1 ExtraOffset 0
sketch "Guide nut rear installation slot (1)" plane through (17.1, 0, 0) normal (1, 0, 0) x axis (0, 0, -1)
  line L1 (-40.8, -55) -> (-40.8, -74.1)
  line L2 (-43.4, -55) -> (-40.8, -55)
  line L3 (-43.4, -74.1) -> (-43.4, -55)
  line L4 (-40.8, -74.1) -> (-43.4, -74.1)
extrude "Extrude66" cut sketch "Guide nut rear installation slot (1)" along normal blind 5.8
work_plane "WorkPlane67" AlongDistance 17.1 ExtraOffset 0
sketch "Guide nut first bridge relief (1)" plane through (17.1, 0, 0) normal (1, 0, 0) x axis (0, 0, -1)
  line L1 (-40.6, -53.3) -> (-40.6, -56.7)
  line L2 (-40.8, -53.3) -> (-40.6, -53.3)
  line L3 (-40.8, -56.7) -> (-40.8, -53.3)
  line L4 (-40.6, -56.7) -> (-40.8, -56.7)
extrude "Extrude67" cut sketch "Guide nut first bridge relief (1)" along normal blind 5.8
work_plane "WorkPlane68" AlongDistance 18.3 ExtraOffset 0
sketch "Guide nut crossed bridge relief (1)" plane through (18.3, 0, 0) normal (1, 0, 0) x axis (0, 0, -1)
  line L1 (-40.4, -53.3) -> (-40.4, -56.7)
  line L2 (-40.6, -53.3) -> (-40.4, -53.3)
  line L3 (-40.6, -56.7) -> (-40.6, -53.3)
  line L4 (-40.4, -56.7) -> (-40.6, -56.7)
extrude "Extrude68" cut sketch "Guide nut crossed bridge relief (1)" along normal blind 3.4
work_plane "WorkPlane1" AlongDistance 40.9 ExtraOffset 0
sketch "Guide nut envelope" plane through (0, 0, 40.9) normal (0, 0, 1) x axis (1, 0, 0)
  line L1 (20, -51.8246) -> (22.75, -53.4123)
  line L2 (17.25, -53.4123) -> (20, -51.8246)
  line L3 (17.25, -56.5877) -> (17.25, -53.4123)
  line L4 (20, -58.1754) -> (17.25, -56.5877)
  line L5 (22.75, -56.5877) -> (20, -58.1754)
  line L6 (22.75, -53.4123) -> (22.75, -56.5877)
extrude "Extrude1" new body sketch "Guide nut envelope" along normal blind 2.4
work_plane "WorkPlane2" AlongDistance 40.8 ExtraOffset 0
sketch "Guide nut thread" plane through (0, 0, 40.8) normal (0, 0, 1) x axis (1, 0, 0)
  circle C1 centre (20, -55) radius 1.5
extrude "Extrude2" cut sketch "Guide nut thread" along normal blind 2.6
work_plane "WorkPlane69" AlongDistance -24 ExtraOffset 0
sketch "Close mounting insert pilot" plane through (-24, 0, 0) normal (1, 0, 0) x axis (0, 0, -1)
  circle C1 centre (-53.5, -62) radius 2.01
extrude "Extrude69" add sketch "Close mounting insert pilot" along normal blind 8.7
work_plane "WorkPlane70" AlongDistance -24.1 ExtraOffset 0
sketch "Block mount screw passage" plane through (-24.1, 0, 0) normal (1, 0, 0) x axis (0, 0, -1)
  circle C1 centre (-53.5, -62) radius 1.7
extrude "Extrude70" cut sketch "Block mount screw passage" along normal blind 8.9
work_plane "WorkPlane71" AlongDistance -20 ExtraOffset 0
sketch "Crossblock captive hex nut" plane through (-20, 0, 0) normal (1, 0, 0) x axis (0, 0, -1)
  line L1 (-56.4, -60.3257) -> (-53.5, -58.6514)
  line L2 (-56.4, -63.6743) -> (-56.4, -60.3257)
  line L3 (-53.5, -65.3486) -> (-56.4, -63.6743)
  line L4 (-50.6, -63.6743) -> (-53.5, -65.3486)
  line L5 (-50.6, -60.3257) -> (-50.6, -63.6743)
  line L6 (-53.5, -58.6514) -> (-50.6, -60.3257)
extrude "Extrude71" cut sketch "Crossblock captive hex nut" along normal blind 2.6
work_plane "WorkPlane72" AlongDistance -20 ExtraOffset 0
sketch "Top installation slot for block nut" plane through (-20, 0, 0) normal (1, 0, 0) x axis (0, 0, -1)
  line L1 (-53.5, -58.65) -> (-53.5, -65.35)
  line L2 (-59.1, -58.65) -> (-53.5, -58.65)
  line L3 (-59.1, -65.35) -> (-59.1, -58.65)
  line L4 (-53.5, -65.35) -> (-59.1, -65.35)
extrude "Extrude72" cut sketch "Top installation slot for block nut" along normal blind 2.6
work_plane "WorkPlane1" AlongDistance -19.9 ExtraOffset 0
sketch "Crossblock captive M3 (-62, -1)" plane through (-19.9, 0, 0) normal (1, 0, 0) x axis (0, 0, -1)
  line L1 (-56.25, -60.4123) -> (-53.5, -58.8246)
  line L2 (-56.25, -63.5877) -> (-56.25, -60.4123)
  line L3 (-53.5, -65.1754) -> (-56.25, -63.5877)
  line L4 (-50.75, -63.5877) -> (-53.5, -65.1754)
  line L5 (-50.75, -60.4123) -> (-50.75, -63.5877)
  line L6 (-53.5, -58.8246) -> (-50.75, -60.4123)
extrude "Extrude1" new body sketch "Crossblock captive M3 (-62, -1)" along normal blind 2.4 bodies "HARDWARE Crossblock captive M3 (-62, -1)"
work_plane "WorkPlane2" AlongDistance -20 ExtraOffset 0
sketch "Thread envelope" plane through (-20, 0, 0) normal (1, 0, 0) x axis (0, 0, -1)
  circle C1 centre (-53.5, -62) radius 1.5
extrude "Extrude2" cut sketch "Thread envelope" along normal blind 2.6
work_plane "WorkPlane73" AlongDistance 15.3 ExtraOffset 0
sketch "Close mounting insert pilot (1)" plane through (15.3, 0, 0) normal (1, 0, 0) x axis (0, 0, -1)
  circle C1 centre (-53.5, -62) radius 2.01
extrude "Extrude73" add sketch "Close mounting insert pilot (1)" along normal blind 8.7
work_plane "WorkPlane74" AlongDistance 15.2 ExtraOffset 0
sketch "Block mount screw passage (1)" plane through (15.2, 0, 0) normal (1, 0, 0) x axis (0, 0, -1)
  circle C1 centre (-53.5, -62) radius 1.7
extrude "Extrude74" cut sketch "Block mount screw passage (1)" along normal blind 8.9
work_plane "WorkPlane75" AlongDistance 17.4 ExtraOffset 0
sketch "Crossblock captive hex nut (1)" plane through (17.4, 0, 0) normal (1, 0, 0) x axis (0, 0, -1)
  line L1 (-56.4, -60.3257) -> (-53.5, -58.6514)
  line L2 (-56.4, -63.6743) -> (-56.4, -60.3257)
  line L3 (-53.5, -65.3486) -> (-56.4, -63.6743)
  line L4 (-50.6, -63.6743) -> (-53.5, -65.3486)
  line L5 (-50.6, -60.3257) -> (-50.6, -63.6743)
  line L6 (-53.5, -58.6514) -> (-50.6, -60.3257)
extrude "Extrude75" cut sketch "Crossblock captive hex nut (1)" along normal blind 2.6
work_plane "WorkPlane76" AlongDistance 17.4 ExtraOffset 0
sketch "Top installation slot for block nut (1)" plane through (17.4, 0, 0) normal (1, 0, 0) x axis (0, 0, -1)
  line L1 (-53.5, -58.65) -> (-53.5, -65.35)
  line L2 (-59.1, -58.65) -> (-53.5, -58.65)
  line L3 (-59.1, -65.35) -> (-59.1, -58.65)
  line L4 (-53.5, -65.35) -> (-59.1, -65.35)
extrude "Extrude76" cut sketch "Top installation slot for block nut (1)" along normal blind 2.6
work_plane "WorkPlane1" AlongDistance 17.5 ExtraOffset 0
sketch "Crossblock captive M3 (-62, 1)" plane through (17.5, 0, 0) normal (1, 0, 0) x axis (0, 0, -1)
  line L1 (-56.25, -60.4123) -> (-53.5, -58.8246)
  line L2 (-56.25, -63.5877) -> (-56.25, -60.4123)
  line L3 (-53.5, -65.1754) -> (-56.25, -63.5877)
  line L4 (-50.75, -63.5877) -> (-53.5, -65.1754)
  line L5 (-50.75, -60.4123) -> (-50.75, -63.5877)
  line L6 (-53.5, -58.8246) -> (-50.75, -60.4123)
extrude "Extrude1" new body sketch "Crossblock captive M3 (-62, 1)" along normal blind 2.4 bodies "HARDWARE Crossblock captive M3 (-62, 1)"
work_plane "WorkPlane2" AlongDistance 17.4 ExtraOffset 0
sketch "Thread envelope" plane through (17.4, 0, 0) normal (1, 0, 0) x axis (0, 0, -1)
  circle C1 centre (-53.5, -62) radius 1.5
extrude "Extrude2" cut sketch "Thread envelope" along normal blind 2.6
work_plane "WorkPlane77" AlongDistance -24 ExtraOffset 0
sketch "Close mounting insert pilot (2)" plane through (-24, 0, 0) normal (1, 0, 0) x axis (0, 0, -1)
  circle C1 centre (-53.5, -70) radius 2.01
extrude "Extrude77" add sketch "Close mounting insert pilot (2)" along normal blind 8.7
work_plane "WorkPlane78" AlongDistance -24.1 ExtraOffset 0
sketch "Block mount screw passage (2)" plane through (-24.1, 0, 0) normal (1, 0, 0) x axis (0, 0, -1)
  circle C1 centre (-53.5, -70) radius 1.7
extrude "Extrude78" cut sketch "Block mount screw passage (2)" along normal blind 8.9
work_plane "WorkPlane79" AlongDistance -20 ExtraOffset 0
sketch "Crossblock captive hex nut (2)" plane through (-20, 0, 0) normal (1, 0, 0) x axis (0, 0, -1)
  line L1 (-56.4, -68.3257) -> (-53.5, -66.6514)
  line L2 (-56.4, -71.6743) -> (-56.4, -68.3257)
  line L3 (-53.5, -73.3486) -> (-56.4, -71.6743)
  line L4 (-50.6, -71.6743) -> (-53.5, -73.3486)
  line L5 (-50.6, -68.3257) -> (-50.6, -71.6743)
  line L6 (-53.5, -66.6514) -> (-50.6, -68.3257)
extrude "Extrude79" cut sketch "Crossblock captive hex nut (2)" along normal blind 2.6
work_plane "WorkPlane80" AlongDistance -20 ExtraOffset 0
sketch "Top installation slot for block nut (2)" plane through (-20, 0, 0) normal (1, 0, 0) x axis (0, 0, -1)
  line L1 (-53.5, -66.65) -> (-53.5, -73.35)
  line L2 (-59.1, -66.65) -> (-53.5, -66.65)
  line L3 (-59.1, -73.35) -> (-59.1, -66.65)
  line L4 (-53.5, -73.35) -> (-59.1, -73.35)
extrude "Extrude80" cut sketch "Top installation slot for block nut (2)" along normal blind 2.6
work_plane "WorkPlane1" AlongDistance -19.9 ExtraOffset 0
sketch "Crossblock captive M3 (-70, -1)" plane through (-19.9, 0, 0) normal (1, 0, 0) x axis (0, 0, -1)
  line L1 (-56.25, -68.4123) -> (-53.5, -66.8246)
  line L2 (-56.25, -71.5877) -> (-56.25, -68.4123)
  line L3 (-53.5, -73.1754) -> (-56.25, -71.5877)
  line L4 (-50.75, -71.5877) -> (-53.5, -73.1754)
  line L5 (-50.75, -68.4123) -> (-50.75, -71.5877)
  line L6 (-53.5, -66.8246) -> (-50.75, -68.4123)
extrude "Extrude1" new body sketch "Crossblock captive M3 (-70, -1)" along normal blind 2.4 bodies "HARDWARE Crossblock captive M3 (-70, -1)"
work_plane "WorkPlane2" AlongDistance -20 ExtraOffset 0
sketch "Thread envelope" plane through (-20, 0, 0) normal (1, 0, 0) x axis (0, 0, -1)
  circle C1 centre (-53.5, -70) radius 1.5
extrude "Extrude2" cut sketch "Thread envelope" along normal blind 2.6
work_plane "WorkPlane81" AlongDistance 15.3 ExtraOffset 0
sketch "Close mounting insert pilot (3)" plane through (15.3, 0, 0) normal (1, 0, 0) x axis (0, 0, -1)
  circle C1 centre (-53.5, -70) radius 2.01
extrude "Extrude81" add sketch "Close mounting insert pilot (3)" along normal blind 8.7
work_plane "WorkPlane82" AlongDistance 15.2 ExtraOffset 0
sketch "Block mount screw passage (3)" plane through (15.2, 0, 0) normal (1, 0, 0) x axis (0, 0, -1)
  circle C1 centre (-53.5, -70) radius 1.7
extrude "Extrude82" cut sketch "Block mount screw passage (3)" along normal blind 8.9
work_plane "WorkPlane83" AlongDistance 17.4 ExtraOffset 0
sketch "Crossblock captive hex nut (3)" plane through (17.4, 0, 0) normal (1, 0, 0) x axis (0, 0, -1)
  line L1 (-56.4, -68.3257) -> (-53.5, -66.6514)
  line L2 (-56.4, -71.6743) -> (-56.4, -68.3257)
  line L3 (-53.5, -73.3486) -> (-56.4, -71.6743)
  line L4 (-50.6, -71.6743) -> (-53.5, -73.3486)
  line L5 (-50.6, -68.3257) -> (-50.6, -71.6743)
  line L6 (-53.5, -66.6514) -> (-50.6, -68.3257)
extrude "Extrude83" cut sketch "Crossblock captive hex nut (3)" along normal blind 2.6
work_plane "WorkPlane84" AlongDistance 17.4 ExtraOffset 0
sketch "Top installation slot for block nut (3)" plane through (17.4, 0, 0) normal (1, 0, 0) x axis (0, 0, -1)
  line L1 (-53.5, -66.65) -> (-53.5, -73.35)
  line L2 (-59.1, -66.65) -> (-53.5, -66.65)
  line L3 (-59.1, -73.35) -> (-59.1, -66.65)
  line L4 (-53.5, -73.35) -> (-59.1, -73.35)
extrude "Extrude84" cut sketch "Top installation slot for block nut (3)" along normal blind 2.6
work_plane "WorkPlane1" AlongDistance 17.5 ExtraOffset 0
sketch "Crossblock captive M3 (-70, 1)" plane through (17.5, 0, 0) normal (1, 0, 0) x axis (0, 0, -1)
  line L1 (-56.25, -68.4123) -> (-53.5, -66.8246)
  line L2 (-56.25, -71.5877) -> (-56.25, -68.4123)
  line L3 (-53.5, -73.1754) -> (-56.25, -71.5877)
  line L4 (-50.75, -71.5877) -> (-53.5, -73.1754)
  line L5 (-50.75, -68.4123) -> (-50.75, -71.5877)
  line L6 (-53.5, -66.8246) -> (-50.75, -68.4123)
extrude "Extrude1" new body sketch "Crossblock captive M3 (-70, 1)" along normal blind 2.4 bodies "HARDWARE Crossblock captive M3 (-70, 1)"
work_plane "WorkPlane2" AlongDistance 17.4 ExtraOffset 0
sketch "Thread envelope" plane through (17.4, 0, 0) normal (1, 0, 0) x axis (0, 0, -1)
  circle C1 centre (-53.5, -70) radius 1.5
extrude "Extrude2" cut sketch "Thread envelope" along normal blind 2.6
work_plane "WorkPlane85" AlongDistance 8.6 ExtraOffset 0
sketch "Preload head first bridge relief" plane through (8.6, 0, 0) normal (1, 0, 0) x axis (0, 0, -1)
  line L1 (-54.8, -53.3) -> (-54.8, -56.7)
  line L2 (-55, -53.3) -> (-54.8, -53.3)
  line L3 (-55, -56.7) -> (-55, -53.3)
  line L4 (-54.8, -56.7) -> (-55, -56.7)
extrude "Extrude85" cut sketch "Preload head first bridge relief" along normal blind 6.8
work_plane "WorkPlane86" AlongDistance 10.3 ExtraOffset 0
sketch "Preload head crossed bridge relief" plane through (10.3, 0, 0) normal (1, 0, 0) x axis (0, 0, -1)
  line L1 (-54.6, -53.3) -> (-54.6, -56.7)
  line L2 (-54.8, -53.3) -> (-54.6, -53.3)
  line L3 (-54.8, -56.7) -> (-54.8, -53.3)
  line L4 (-54.6, -56.7) -> (-54.8, -56.7)
extrude "Extrude86" cut sketch "Preload head crossed bridge relief" along normal blind 3.4
work_plane "WorkPlane9" AlongDistance -9 ExtraOffset 0
sketch "Close sensor clamp insert pilot" plane through (0, -9, 0) normal (0, 1, 0) x axis (1, 0, 0)
  circle C1 centre (54.15, -73) radius 2.01
extrude "Extrude9" add sketch "Close sensor clamp insert pilot" along normal blind 8.9
work_plane "WorkPlane10" AlongDistance -9.1 ExtraOffset 0
sketch "Sensor clamp M3 clearance" plane through (0, -9.1, 0) normal (0, 1, 0) x axis (1, 0, 0)
  circle C1 centre (54.15, -73) radius 1.7
extrude "Extrude10" cut sketch "Sensor clamp M3 clearance" along normal blind 9.1
work_plane "WorkPlane11" AlongDistance -6.9 ExtraOffset 0
sketch "Sensor clamp captive hex nut" plane through (0, -6.9, 0) normal (0, 1, 0) x axis (1, 0, 0)
  line L1 (55.8243, -75.9) -> (57.4986, -73)
  line L2 (52.4757, -75.9) -> (55.8243, -75.9)
  line L3 (50.8014, -73) -> (52.4757, -75.9)
  line L4 (52.4757, -70.1) -> (50.8014, -73)
  line L5 (55.8243, -70.1) -> (52.4757, -70.1)
  line L6 (57.4986, -73) -> (55.8243, -70.1)
extrude "Extrude11" cut sketch "Sensor clamp captive hex nut" along normal blind 2.6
